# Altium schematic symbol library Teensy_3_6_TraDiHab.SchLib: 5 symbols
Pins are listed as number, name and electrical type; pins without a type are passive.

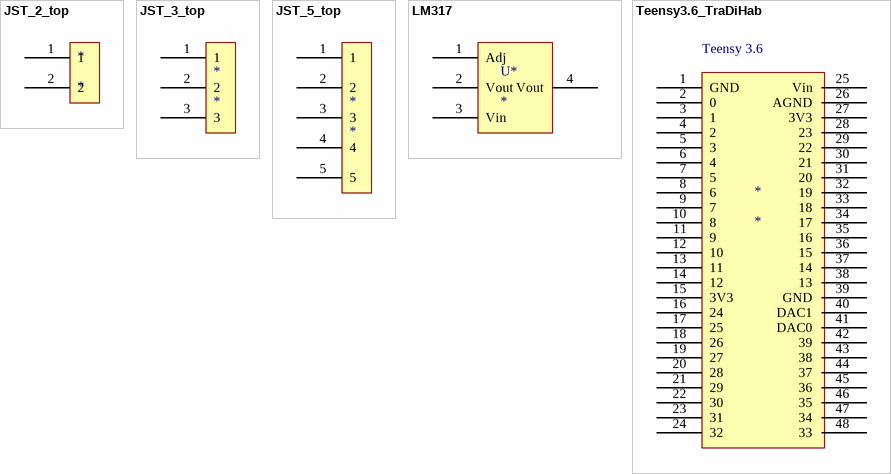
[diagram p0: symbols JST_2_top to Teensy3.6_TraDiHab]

## JST_2_top
designator *
footprint JST_2_top
pins: 1, 2

## JST_3_top
designator *
footprint JST_3_top
pins: 1, 2, 3

## JST_5_top
designator *
footprint JST_5_top
pins: 1, 2, 3, 4, 5

## LM317
designator U*
footprint SOT223_N (SOT223, 4-Leads, Body 6.5x3.5mm, Pitch 2.3mm, Lead Span 7mm, IPC Medium Density)
pins: 1 Adj, 2 Vout, 3 Vin, 4 Vout

## Teensy3.6_TraDiHab
designator *
footprint teensy3_6footprint
pins: 1 GND, 2 0, 3 1, 4 2, 5 3, 6 4, 7 5, 8 6, 9 7, 10 8, 11 9, 12 10, 13 11, 14 12, 15 3V3, 16 24, 17 25, 18 26, 19 27, 20 28, 21 29, 22 30, 23 31, 24 32, 25 Vin, 26 AGND, 27 3V3, 28 23, 29 22, 30 21, 31 20, 32 19, 33 18, 34 17, 35 16, 36 15, 37 14, 38 13, 39 GND, 40 DAC1, 41 DAC0, 42 39, 43 38, 44 37, 45 36, 46 35, 47 34, 48 33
